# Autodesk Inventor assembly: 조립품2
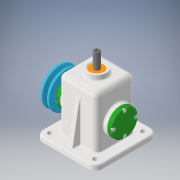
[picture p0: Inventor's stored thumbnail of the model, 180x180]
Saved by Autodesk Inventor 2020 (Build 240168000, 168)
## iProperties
Created: 2022-11
Part Number: 조립품2
Document SubType Name: Assembly
Designer: com
Author: com
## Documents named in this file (11)
- C:\Users\com\Desktop\조립품2.iam
- C:\Users\com\Desktop\부품.ipt
- C:\Users\com\Desktop\뒤커버.ipt
- C:\Users\com\Desktop\편심축.ipt
- C:\Users\com\Desktop\부시.ipt
- C:\Users\com\Desktop\앞커버.ipt
- C:\Users\com\Desktop\V벨트풀리.ipt
- C:\Users\com\Desktop\베어링 6201.ipt
- C:\Users\com\Desktop\멈춤나사 M3 x 8.ipt
- C:\Users\com\Desktop\슬라이드.ipt
- C:\Users\com\Desktop\볼트 M4 x 12.ipt
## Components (5 placed, 2 different names)
1. V벨트풀리:1
2. ISO 4762 M4 x 12:1
3. ISO 4762 M4 x 12:2
4. ISO 4762 M4 x 12:3
5. ISO 4762 M4 x 12:4
